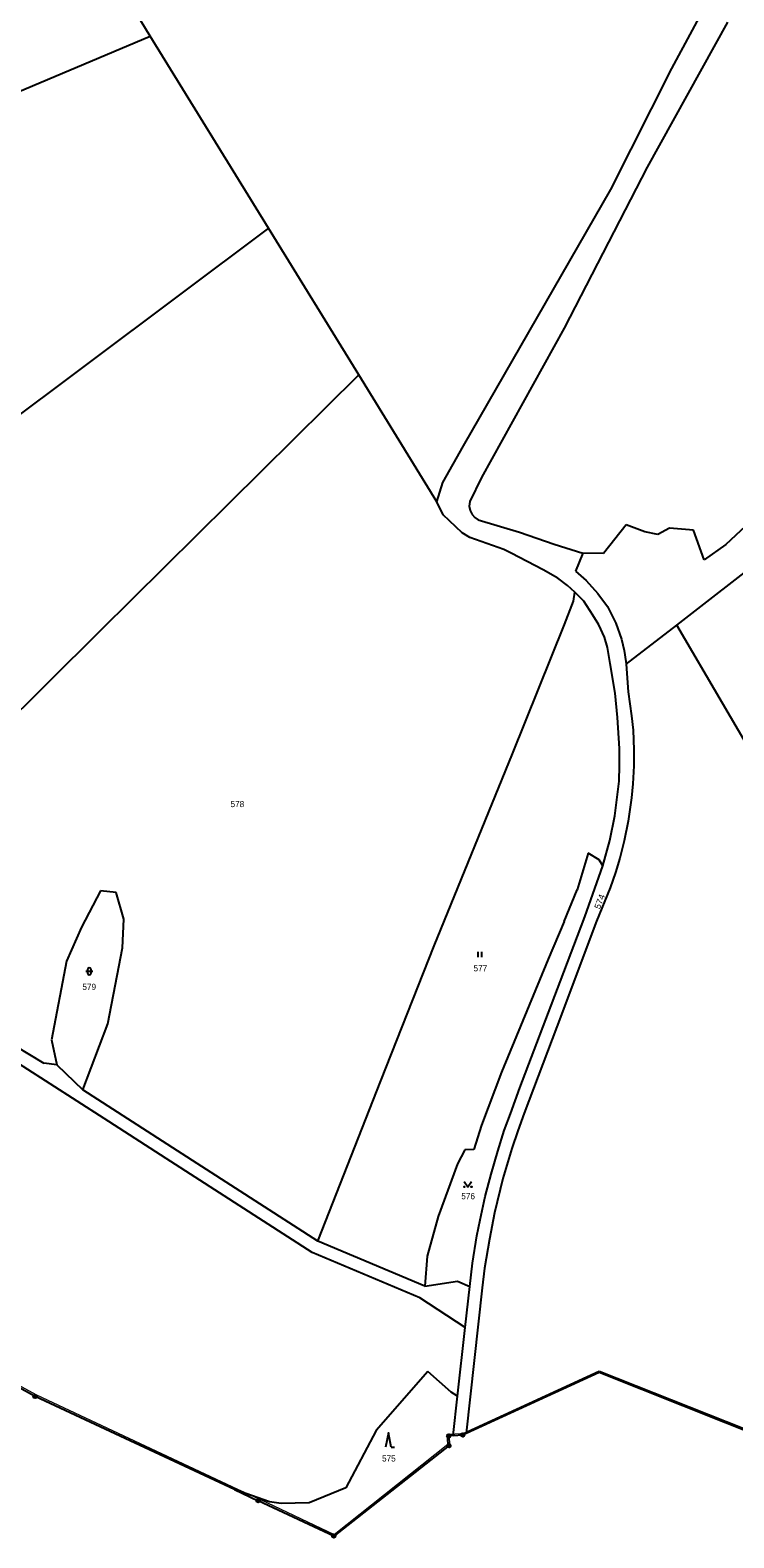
# Model space of a CAD drawing. Extents: x -653193 to -651624, y -1092017 to -1090260.
# Drawn here: x -652842.7 to -652647.5, y -1092016.6 to -1091598.3 of the extents above; entities that cross this region are included whole.
import ezdxf
from ezdxf.enums import TextEntityAlignment as Align

# ---------------------------------------------------------------- set-up
doc = ezdxf.new("R2010")
doc.units = 0
doc.header["$LTSCALE"] = 0.68
for name, color, linetype, lineweight in [('1', 7, 'Continuous', 25), ('3', 7, 'Continuous', 25), ('4', 7, 'Continuous', 13), ('8', 7, 'Continuous', 25)]:
    doc.layers.add(name, color=color, linetype=linetype, lineweight=lineweight)
doc.layers.add('2', color=7, linetype='Continuous')

msp = doc.modelspace()

# ---------------------------------------------------------------- linework, layer by layer
at = {"layer": '1'}
for p, q in [((-652809.38, -1091599.93), (-652836.23, -1091556.01)), ((-652664.65, -1091608.9), (-652648.66, -1091579.28)), ((-652649.19, -1091596.08), (-652671.5, -1091636.35)), ((-652892.48, -1091635), (-652809.38, -1091599.93)), ((-652776.6, -1091653.24), (-652809.38, -1091599.93)), ((-652681.61, -1091642.51), (-652664.65, -1091608.9)), ((-652671.5, -1091636.35), (-652694.51, -1091680.94)), ((-652722.47, -1091713.65), (-652681.61, -1091642.51)), ((-652776.6, -1091653.24), (-652865.28, -1091719.6)), ((-652751.49, -1091693.97), (-652776.6, -1091653.24)), ((-652663.3, -1091763.35), (-652538.01, -1091666.2)), ((-652694.51, -1091680.94), (-652717.44, -1091722.44)), ((-652823.28, -1091765), (-652751.49, -1091693.97)), ((-652729.91, -1091729.13), (-652751.49, -1091693.97)), ((-652728.24, -1091723.76), (-652722.47, -1091713.65)), ((-652729.91, -1091729.13), (-652728.24, -1091723.76)), ((-652717.44, -1091722.44), (-652720.74, -1091729.11)), ((-652728.13, -1091732.82), (-652729.91, -1091729.13)), ((-652720.74, -1091729.11), (-652720.87, -1091730.41)), ((-652722.82, -1091737.76), (-652728.13, -1091732.82)), ((-652720.87, -1091730.41), (-652720.67, -1091731.6)), ((-652720.67, -1091731.6), (-652720.1, -1091732.7)), ((-652720.1, -1091732.7), (-652719.34, -1091733.52)), ((-652719.34, -1091733.52), (-652718.4, -1091734.12)), ((-652641.56, -1091733.43), (-652649.7, -1091740.97)), ((-652720.73, -1091739.1), (-652722.82, -1091737.76)), ((-652718.4, -1091734.12), (-652706.92, -1091737.61)), ((-652706.92, -1091737.61), (-652697.29, -1091740.95)), ((-652677.38, -1091735.59), (-652683.6, -1091743.47)), ((-652672.17, -1091737.48), (-652677.38, -1091735.59)), ((-652668.6, -1091738.24), (-652672.17, -1091737.48)), ((-652665.3, -1091736.48), (-652668.6, -1091738.24)), ((-652658.65, -1091737.06), (-652665.3, -1091736.48)), ((-652655.73, -1091745.28), (-652658.65, -1091737.06)), ((-652711.3, -1091742.43), (-652720.73, -1091739.1)), ((-652697.29, -1091740.95), (-652689.41, -1091743.4)), ((-652649.7, -1091740.97), (-652655.73, -1091745.28)), ((-652709.26, -1091743.38), (-652711.3, -1091742.43)), ((-652700.4, -1091748.03), (-652709.26, -1091743.38)), ((-652689.41, -1091743.4), (-652691.42, -1091748.41)), ((-652683.6, -1091743.47), (-652689.41, -1091743.4)), ((-652696.26, -1091750.39), (-652700.4, -1091748.03)), ((-652691.42, -1091748.41), (-652688.41, -1091751)), ((-652693.59, -1091752.34), (-652696.26, -1091750.39)), ((-652691.6, -1091754.24), (-652693.59, -1091752.34)), ((-652691.91, -1091756.77), (-652691.6, -1091754.24)), ((-652689.12, -1091756.76), (-652691.6, -1091754.24)), ((-652688.41, -1091751), (-652685.17, -1091754.61)), ((-652694.43, -1091763.16), (-652691.91, -1091756.77)), ((-652686.59, -1091760.61), (-652689.12, -1091756.76)), ((-652685.17, -1091754.61), (-652682.48, -1091758.23)), ((-652682.48, -1091758.23), (-652680.22, -1091762.79)), ((-652684.9, -1091763.33), (-652686.59, -1091760.61)), ((-652680.22, -1091762.79), (-652678.62, -1091767.31)), ((-652903.41, -1091844.28), (-652823.28, -1091765)), ((-652708.9, -1091799.06), (-652694.43, -1091763.16)), ((-652683.38, -1091766.76), (-652684.9, -1091763.33)), ((-652682.5, -1091769.62), (-652683.38, -1091766.76)), ((-652677.34, -1091774.24), (-652663.3, -1091763.35)), ((-652637.66, -1091807.25), (-652663.3, -1091763.35)), ((-652681.74, -1091774.01), (-652682.5, -1091769.62)), ((-652678.62, -1091767.31), (-652677.89, -1091770.41)), ((-652677.89, -1091770.41), (-652677.39, -1091773.5)), ((-652680.41, -1091782.27), (-652681.74, -1091774.01)), ((-652677.39, -1091773.5), (-652677.34, -1091774.24)), ((-652677.34, -1091774.24), (-652676.8, -1091781.85)), ((-652679.79, -1091788.96), (-652680.41, -1091782.27)), ((-652676.8, -1091781.85), (-652675.88, -1091788.51)), ((-652679.17, -1091797.64), (-652679.79, -1091788.96)), ((-652675.88, -1091788.51), (-652675.42, -1091792.5)), ((-652675.42, -1091792.5), (-652675.19, -1091797.99)), ((-652730.58, -1091852.32), (-652708.9, -1091799.06)), ((-652679.17, -1091802.31), (-652679.17, -1091797.64)), ((-652675.19, -1091797.99), (-652675.22, -1091802.38)), ((-652679.32, -1091806.67), (-652679.17, -1091802.31)), ((-652675.22, -1091802.38), (-652675.46, -1091807.45)), ((-652680.52, -1091816.33), (-652679.32, -1091806.67)), ((-652675.46, -1091807.45), (-652675.82, -1091811.27)), ((-652675.82, -1091811.27), (-652676.79, -1091817.79)), ((-652681.84, -1091823.09), (-652680.52, -1091816.33)), ((-652676.79, -1091817.79), (-652677.88, -1091823.21)), ((-652683.81, -1091830.11), (-652681.84, -1091823.09)), ((-652677.88, -1091823.21), (-652679.1, -1091828.02)), ((-652687.87, -1091826.67), (-652690.94, -1091836.84)), ((-652684.86, -1091828.53), (-652687.87, -1091826.67)), ((-652683.81, -1091830.11), (-652684.86, -1091828.53)), ((-652679.1, -1091828.02), (-652680.32, -1091832.03)), ((-652685.48, -1091834.86), (-652683.81, -1091830.11)), ((-652680.32, -1091832.03), (-652681.8, -1091836.24)), ((-652823.17, -1091837.08), (-652828.43, -1091847.13)), ((-652818.89, -1091837.52), (-652823.17, -1091837.08)), ((-652816.68, -1091844.91), (-652818.89, -1091837.52)), ((-652694.56, -1091845.63), (-652690.94, -1091836.84)), ((-652688.83, -1091844.32), (-652685.48, -1091834.86)), ((-652681.8, -1091836.24), (-652685.53, -1091845.5)), ((-652817.12, -1091852.93), (-652816.68, -1091844.91)), ((-652694.56, -1091845.63), (-652698.96, -1091856.09)), ((-652685.53, -1091845.5), (-652696.6, -1091874.79)), ((-652695.67, -1091862.3), (-652688.83, -1091844.32)), ((-652828.43, -1091847.13), (-652832.61, -1091856.6)), ((-652818.56, -1091860.56), (-652817.12, -1091852.93)), ((-652745.39, -1091889.81), (-652730.58, -1091852.32)), ((-652832.61, -1091856.6), (-652836.77, -1091878.39)), ((-652698.96, -1091856.09), (-652711.9, -1091887.39)), ((-652821.18, -1091873.95), (-652818.56, -1091860.56)), ((-652706.83, -1091891.79), (-652695.67, -1091862.3)), ((-652828.14, -1091892.34), (-652821.18, -1091873.95)), ((-652696.6, -1091874.79), (-652705.68, -1091898.79)), ((-652850.84, -1091877.72), (-652838.95, -1091884.94)), ((-652836.77, -1091878.39), (-652835.34, -1091885.36)), ((-652822.22, -1091900.29), (-652852.73, -1091880.67)), ((-652835.34, -1091885.36), (-652838.95, -1091884.94)), ((-652835.34, -1091885.36), (-652828.14, -1091892.34)), ((-652711.9, -1091887.39), (-652717.46, -1091902.09)), ((-652801.83, -1091909.25), (-652828.14, -1091892.34)), ((-652762.87, -1091934.29), (-652745.39, -1091889.81)), ((-652709.4, -1091899), (-652706.83, -1091891.79)), ((-652803.72, -1091912.19), (-652822.22, -1091900.29)), ((-652711.19, -1091903.59), (-652709.4, -1091899)), ((-652705.68, -1091898.79), (-652707.4, -1091903.66)), ((-652717.46, -1091902.09), (-652719.64, -1091908.9)), ((-652712.98, -1091909.3), (-652711.19, -1091903.59)), ((-652707.4, -1091903.66), (-652709.07, -1091908.61)), ((-652762.87, -1091934.29), (-652801.83, -1091909.25)), ((-652722.09, -1091908.96), (-652724.15, -1091912.86)), ((-652719.64, -1091908.9), (-652722.09, -1091908.96)), ((-652714.81, -1091915.68), (-652712.98, -1091909.3)), ((-652709.07, -1091908.61), (-652711.56, -1091916.89)), ((-652764.51, -1091937.4), (-652803.72, -1091912.19)), ((-652724.15, -1091912.86), (-652729.54, -1091927.43)), ((-652716.45, -1091921.86), (-652714.81, -1091915.68)), ((-652711.56, -1091916.89), (-652713.88, -1091926.4)), ((-652717.87, -1091928.33), (-652716.45, -1091921.86)), ((-652729.54, -1091927.43), (-652732.56, -1091938.48)), ((-652718.73, -1091932.77), (-652717.87, -1091928.33)), ((-652713.88, -1091926.4), (-652715.3, -1091933.75)), ((-652733.2, -1091946.82), (-652762.87, -1091934.29)), ((-652719.94, -1091940.43), (-652718.73, -1091932.77)), ((-652715.3, -1091933.75), (-652716.63, -1091941.75)), ((-652734.56, -1091950.04), (-652764.51, -1091937.4)), ((-652732.56, -1091938.48), (-652733.2, -1091946.82)), ((-652720.76, -1091946.87), (-652719.94, -1091940.43)), ((-652716.63, -1091941.75), (-652717.31, -1091947.2)), ((-652733.2, -1091946.82), (-652724.13, -1091945.35)), ((-652724.13, -1091945.35), (-652720.76, -1091946.87)), ((-652721.99, -1091958.2), (-652720.76, -1091946.87)), ((-652721.99, -1091958.2), (-652734.56, -1091950.04)), ((-652717.31, -1091947.2), (-652721.71, -1091987.59)), ((-652724.11, -1091977.29), (-652721.99, -1091958.2)), ((-652732.39, -1091970.47), (-652746.69, -1091986.82)), ((-652725.9, -1091976.2), (-652732.39, -1091970.47)), ((-652721.71, -1091987.59), (-652684.85, -1091970.65)), ((-652684.85, -1091970.65), (-652604.79, -1092002.52)), ((-652724.11, -1091977.29), (-652725.9, -1091976.2)), ((-652786.02, -1092003.22), (-652841.35, -1091977.39)), ((-652725.31, -1091988.24), (-652724.11, -1091977.29)), ((-652746.69, -1091986.82), (-652755.09, -1092002.69)), ((-652725.31, -1091988.24), (-652726.58, -1091988.34)), ((-652726.58, -1091988.34), (-652726.49, -1091991.01)), ((-652725.31, -1091988.24), (-652722.69, -1091988.04)), ((-652722.69, -1091988.04), (-652721.71, -1091987.59)), ((-652726.49, -1091991.01), (-652758.44, -1092016.1)), ((-652776.29, -1092006.64), (-652786.02, -1092003.22)), ((-652786.02, -1092003.22), (-652779.45, -1092006.29)), ((-652755.09, -1092002.69), (-652765.34, -1092006.91)), ((-652758.44, -1092016.1), (-652779.45, -1092006.29)), ((-652773.11, -1092007.1), (-652776.29, -1092006.64)), ((-652765.34, -1092006.91), (-652773.11, -1092007.1))]:
    msp.add_line(p, q, dxfattribs=at)
msp.add_lwpolyline([(-652841.35, -1091977.39), (-652884.55, -1091953.7), (-652922.45, -1091926.82)], dxfattribs=at)
at = {"layer": '3'}
for p, q in [((-652718.361, -1091855.48), (-652718.361, -1091853.98)), ((-652717.36, -1091855.48), (-652717.36, -1091853.98)), ((-652826.801, -1091858.921), (-652826.801, -1091859.922)), ((-652825.799, -1091859.922), (-652825.799, -1091858.921)), ((-652827.301, -1091859.421), (-652825.299, -1091859.421)), ((-652742.58, -1091991.47), (-652741.584, -1091991.47))]:
    msp.add_line(p, q, dxfattribs=at)
for points in [[(-652722.25, -1091917.719), (-652721.25, -1091919.22), (-652720.25, -1091917.719)], [(-652742.58, -1091991.47), (-652743.33, -1091987.47), (-652744.08, -1091991.47)]]:
    msp.add_lwpolyline(points, dxfattribs=at)
for centre in [(-652722.25, -1091919.2195), (-652720.25, -1091919.2195)]:
    msp.add_circle(centre, 0.1, dxfattribs=at)
for centre, start, end in [((-652826.3, -1091858.9209), 0, 180), ((-652826.3, -1091859.9209), 180, 359.98789)]:
    msp.add_arc(centre, 0.5, start, end, dxfattribs=at)
at = {"layer": '4'}
msp.add_lwpolyline([(-653077.75, -1091583), (-653070.49, -1091617.25), (-653064.62, -1091618.93), (-653062.8, -1091647.54), (-653053.06, -1091691.15), (-653042.85, -1091739.69), (-653024.99, -1091808.05), (-653012.25, -1091836.33), (-652976.82, -1091876.16), (-652967.99, -1091886.1), (-652922.02, -1091926.56), (-652884.11, -1091953.46), (-652840.95, -1091976.96), (-652785.14, -1092003.14), (-652778.84, -1092006), (-652758.36, -1092015.7), (-652726.85, -1091990.62), (-652727, -1091987.85), (-652722.65, -1091987.61), (-652684.79, -1091970.22), (-652604.59, -1092002.09)], dxfattribs=at)
at = {"layer": '8'}
for centre, radius in [((-652841.35, -1091977.3899), 0.5), ((-652841.35, -1091977.3899), 0.0303), ((-652726.58, -1091988.3399), 0.5), ((-652726.58, -1091988.3399), 0.0303), ((-652722.69, -1091988.0399), 0.5), ((-652722.69, -1091988.0399), 0.0303), ((-652726.49, -1091991.0099), 0.5), ((-652726.49, -1091991.0099), 0.0303), ((-652779.45, -1092006.2899), 0.5), ((-652779.45, -1092006.2899), 0.0303), ((-652758.44, -1092016.0999), 0.5), ((-652758.44, -1092016.0999), 0.0303)]:
    msp.add_circle(centre, radius, dxfattribs=at)

# ---------------------------------------------------------------- texts
at = {"layer": '2'}
for s, p in [('578', (-652785.219, -1091813.865)), ('577', (-652717.789, -1091859.415)), ('579', (-652826.329, -1091864.575)), ('576', (-652721.189, -1091922.665)), ('575', (-652743.179, -1091995.415))]:
    msp.add_text(s, height=1.7, dxfattribs=at).set_placement(p, align=Align.CENTER)
at = {"layer": '2', "width": 1.1}
msp.add_text('574', height=1.7, rotation=69, dxfattribs=at).set_placement((-652683.9128, -1091840.3766), align=Align.CENTER)

doc.saveas('drawing.dxf')
